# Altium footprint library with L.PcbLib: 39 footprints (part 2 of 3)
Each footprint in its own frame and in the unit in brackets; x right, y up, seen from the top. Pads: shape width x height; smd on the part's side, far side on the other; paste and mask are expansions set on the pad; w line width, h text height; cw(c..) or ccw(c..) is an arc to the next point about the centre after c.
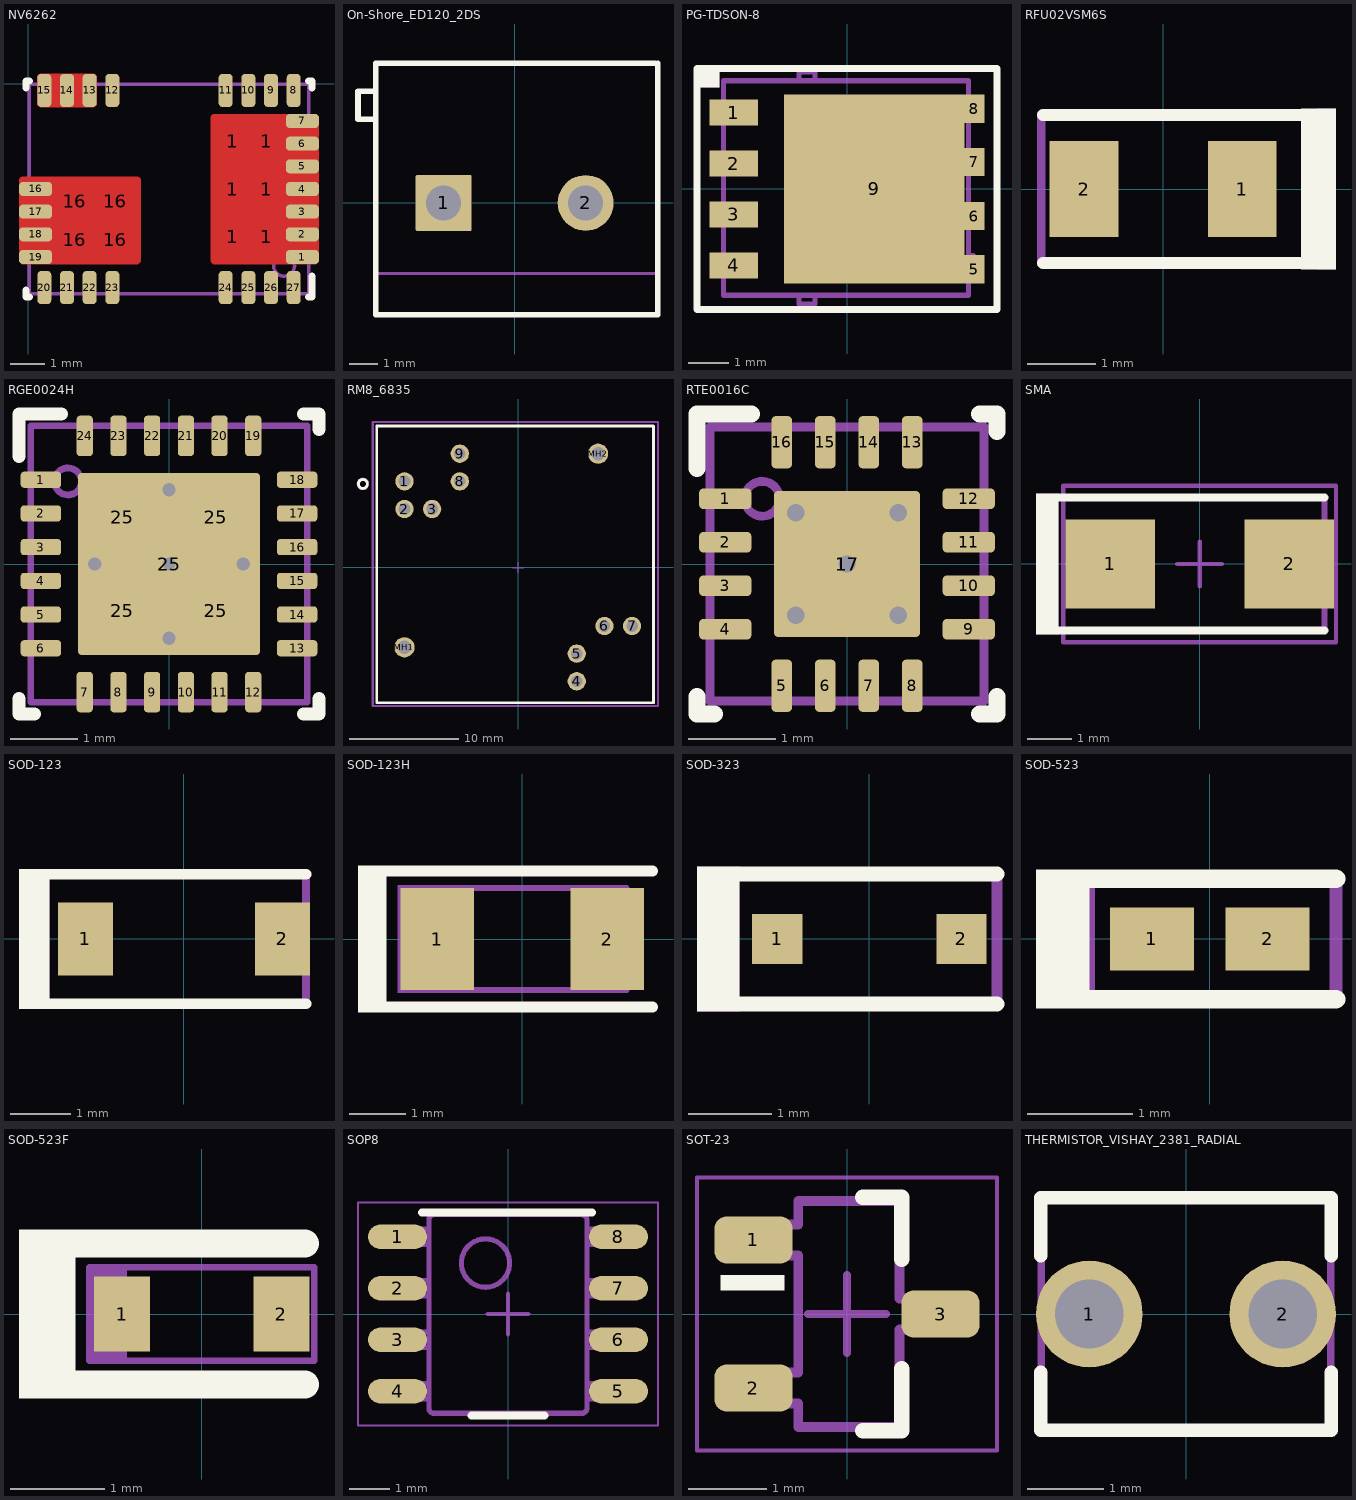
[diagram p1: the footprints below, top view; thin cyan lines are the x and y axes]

## NV6262 [mm]
pads (37):
  rrect50% 0.78x1.17 on Top Paste: 1(5.858,-4.384) 1(5.858,-3.014) 1(5.858,-1.644) 1(6.838,-4.384) 1(6.838,-3.014) 1(6.838,-1.644)
  rrect55% 0.95x0.4 smd paste-0.05 mask-0.05: 1(7.858,-4.964) 2(7.858,-4.314) 3(7.858,-3.664) 4(7.858,-3.014) 5(7.858,-2.364) 6(7.858,-1.714) 7(7.858,-1.064) 16(0.208,-3.014) 17(0.208,-3.664) 18(0.208,-4.314) 19(0.208,-4.964)
  rrect55% 0.4x0.95 smd paste-0.05 mask-0.05: 8(7.608,-0.189) 9(6.958,-0.189) 10(6.308,-0.189) 11(5.658,-0.189) 12(2.408,-0.189) 13(1.758,-0.189) 14(1.108,-0.189) 15(0.458,-0.189) 20(0.458,-5.839) 21(1.108,-5.839) 22(1.758,-5.839) 23(2.408,-5.839) 24(5.658,-5.839) 25(6.308,-5.839) 26(6.958,-5.839) 27(7.608,-5.839)
  rrect50% 0.96x0.9 on Top Paste: 16(1.333,-4.464) 16(1.333,-3.364) 16(2.493,-4.464) 16(2.493,-3.364)
Top Layer:
  region: 1.958,0.186 1.958,-0.564 1.958,-0.584 1.943,-0.621 1.915,-0.649 1.878,-0.664 1.858,-0.664 0.358,-0.664 0.339,-0.664 0.302,-0.649 0.274,-0.621 0.258,-0.584 0.258,-0.564 0.258,0.186 0.258,0.206 0.274,0.242 0.302,0.271 0.339,0.286 0.358,0.286 1.858,0.286 1.878,0.286 1.915,0.271 1.943,0.242 1.958,0.206
  region: 8.333,-0.964 8.333,-5.064 8.333,-5.084 8.318,-5.121 8.29,-5.149 8.253,-5.164 8.233,-5.164 5.323,-5.164 5.304,-5.164 5.267,-5.149 5.239,-5.121 5.223,-5.084 5.223,-5.064 5.223,-0.964 5.223,-0.944 5.239,-0.908 5.267,-0.879 5.304,-0.864 5.323,-0.864 8.233,-0.864 8.253,-0.864 8.29,-0.879 8.318,-0.908 8.333,-0.944
  region: 3.223,-2.764 3.223,-5.064 3.223,-5.084 3.208,-5.121 3.18,-5.149 3.143,-5.164 3.123,-5.164 -0.167,-5.164 -0.186,-5.164 -0.223,-5.149 -0.251,-5.121 -0.267,-5.084 -0.267,-5.064 -0.267,-2.764 -0.267,-2.744 -0.251,-2.708 -0.223,-2.679 -0.186,-2.664 -0.167,-2.664 3.123,-2.664 3.143,-2.664 3.18,-2.679 3.208,-2.708 3.223,-2.744
Top Overlay:
  lines w0.2: -0.067,-5.914 -0.067,-6.114 0.033,-6.114 ; -0.067,-0.114 -0.067,0.086 0.033,0.086 ; 8.033,-6.114 8.133,-6.114 8.133,-5.514 ; 8.033,0.086 8.133,0.086 8.133,-0.114
Top Paste:
  region: 1.759,-0.164 0.459,-0.164 0.459,-0.614 1.759,-0.614
Top Solder:
  region: 7.533,-4.814 7.233,-4.814 7.233,-5.114 7.533,-5.114
  region: 7.533,-4.164 7.233,-4.164 7.233,-4.464 7.533,-4.464
  region: 7.533,-3.514 7.233,-3.514 7.233,-3.814 7.533,-3.814
  region: 7.533,-2.864 7.233,-2.864 7.233,-3.164 7.533,-3.164
  region: 7.533,-2.214 7.233,-2.214 7.233,-2.514 7.533,-2.514
  region: 7.533,-1.564 7.233,-1.564 7.233,-1.864 7.533,-1.864
  region: 7.533,-0.914 7.233,-0.914 7.233,-1.214 7.533,-1.214
  region: 0.834,-4.164 0.534,-4.164 0.534,-4.464 0.834,-4.464
  region: 0.834,-4.814 0.534,-4.814 0.534,-5.114 0.834,-5.114
  region: 0.834,-3.514 0.534,-3.514 0.534,-3.814 0.834,-3.814
  region: 0.834,-2.864 0.534,-2.864 0.534,-3.164 0.834,-3.164
  region: 1.759,-0.164 0.459,-0.164 0.459,-0.614 1.759,-0.614
  region: 7.433,-0.964 7.433,-5.064 7.433,-5.074 7.426,-5.093 7.412,-5.107 7.393,-5.114 7.383,-5.114 5.323,-5.114 5.313,-5.114 5.295,-5.107 5.281,-5.093 5.273,-5.074 5.273,-5.064 5.273,-0.964 5.273,-0.954 5.281,-0.936 5.295,-0.922 5.313,-0.914 5.323,-0.914 7.383,-0.914 7.393,-0.914 7.412,-0.922 7.426,-0.936 7.433,-0.954
  region: 3.173,-2.764 3.173,-5.064 3.173,-5.074 3.166,-5.093 3.152,-5.107 3.133,-5.114 3.123,-5.114 0.683,-5.114 0.673,-5.114 0.655,-5.107 0.641,-5.093 0.633,-5.074 0.633,-5.064 0.633,-2.764 0.633,-2.754 0.641,-2.736 0.655,-2.722 0.673,-2.714 0.683,-2.714 3.123,-2.714 3.133,-2.714 3.152,-2.722 3.166,-2.736 3.173,-2.754
Mechanical 6:
  circle w0.1: c7.333,-5.214 r0.3
  lines w0.1: 0.033,-6.014 8.033,-6.014 8.033,-0.014 0.033,-0.014 0.033,-6.014
  text ".Designator" at 9.29,-2.159 h1.02
3D body: height 0.9, standoff 0, extent 0.033,-6.014 8.033,-0.014
3D body: height 0.91, standoff 0.9, extent 7.034,-5.514 7.633,-4.915

## On-Shore_ED120_2DS [mm] "ONSHORE"
height 13
pads (2):
  rrect5% 2x2 hole 1.25: 1(-2.54,0)
  round 2 hole 1.25: 2(2.54,0)
Top Overlay:
  lines w0.2: -4.96,-4 -4.96,5 5.015,5 ; -4.96,3 -5.6,3 -5.6,4 -4.96,4 ; -4.885,-4 5.115,-4 5.115,5
Mechanical 5:
  lines w0.1: -4.96,-4 -4.96,5 5.115,5 5.115,-4 -4.885,-4 ; -4.96,3 -5.6,3 -5.6,4 -4.96,4 ; -4.875,-2.525 5.125,-2.525
3D body "ED1202DS.stp": height 13, standoff -4, extent -5.78,-4 5.08,5

## PG-TDSON-8 [mm] "Infineon recommended land pattern"
height 1.1
pads (9):
  rect 1.2x0.65 smd: 1(-2.825,1.905) 2(-2.825,0.635) 3(-2.825,-0.635) 4(-2.825,-1.905)
  rect 0.5x0.7 smd: 5(3.175,-2) 6(3.175,-0.675) 7(3.175,0.675) 8(3.175,2)
  rect 4.5x4.7 smd paste-2.25: 9(0.675,0)
Top Overlay:
  rectangle: -3.74,2.527 -3.175,2.975
  lines w0.178: -3.74,-3 -0.105,-3 3.74,-3 3.74,0 3.74,3 0.105,3 -3.74,3 -3.74,0 -3.74,-3
Top Paste:
  rectangle: -1.475,-2.25 -0.242,-0.95
  rectangle: 0.058,-2.25 1.291,-0.95
  rectangle: 1.591,-2.25 2.824,-0.95
  rectangle: 1.591,-0.65 2.824,0.65
  rectangle: 0.058,-0.65 1.291,0.65
  rectangle: -1.475,-0.65 -0.242,0.65
  rectangle: 1.591,0.95 2.824,2.25
  rectangle: 0.058,0.95 1.291,2.25
  rectangle: -1.475,0.95 -0.242,2.25
Mechanical 5:
  rectangle: -3.74,2.527 -3.175,2.975
  lines w0.127: -3.075,-2.1 -3.2,-2.1 -3.2,-1.66 -3.075,-1.66 ; -3.075,-0.83 -3.2,-0.83 -3.2,-0.39 -3.075,-0.39 ; -3.075,0.44 -3.2,0.44 -3.2,0.88 -3.075,0.88 ; -3.075,1.71 -3.2,1.71 -3.2,2.15 -3.075,2.15 ; -1.2,-2.65 -1.2,-2.87 -0.8,-2.87 -0.8,-2.65 ; -1.2,2.7 -1.2,2.92 -0.8,2.92 -0.8,2.7 ; 3.025,-2.1 3.15,-2.1 3.15,-1.66 3.025,-1.66 ; 3.025,-0.83 3.15,-0.83 3.15,-0.39 3.025,-0.39 ; 3.025,0.44 3.15,0.44 3.15,0.88 3.025,0.88 ; 3.025,1.71 3.15,1.71 3.15,2.15 3.025,2.15 ; -3.075,-2.65 -3.075,2.7 3.025,2.7 3.025,-2.65 -3.075,-2.65
3D body "PG-TDSON-8.stp": height 1.1, standoff 0, extent -3.175,-2.895 3.175,2.895

## RFU02VSM6S [mm] "On Semi recommended land pattern"
height 1.35
pads (2):
  rect 1x1.4 smd: 1(1.15,0) 2(-1.15,0)
Top Overlay:
  region: 2.515,1.168 2.007,1.168 2.007,-1.168 2.515,-1.168
  lines w0.178: -1.75,-1.075 2.4,-1.075 ; -1.75,1.075 2.425,1.075
Mechanical 6:
  region: 2.489,1.169 2.235,1.169 2.235,-1.168 2.489,-1.168
  lines w0.127: -1.775,1.075 2.45,1.075 ; -1.775,1.084 -1.775,-1.075 2.413,-1.079
  text ".Designator" at 1.956,0.33 h0.76
3D body "SOD-123.stp": height 1.35, standoff 0, extent -1.932,-0.9 1.932,0.9

## RGE0024H [mm] "QFN, 24-Leads, Body 4x4mm, Pitch 0.5mm, Thermal Pad 2.7x2.7mm, TI Recommended"
height 1
pads (29):
  rrect42% 0.6x0.24 smd: 1(-1.9,1.25) 2(-1.9,0.75) 3(-1.9,0.25) 4(-1.9,-0.25) 5(-1.9,-0.75) 6(-1.9,-1.25) 13(1.9,-1.25) 14(1.9,-0.75) 15(1.9,-0.25) 16(1.9,0.25) 17(1.9,0.75) 18(1.9,1.25)
  rrect42% 0.24x0.6 smd: 7(-1.25,-1.9) 8(-0.75,-1.9) 9(-0.25,-1.9) 10(0.25,-1.9) 11(0.75,-1.9) 12(1.25,-1.9) 19(1.25,1.9) 20(0.75,1.9) 21(0.25,1.9) 22(-0.25,1.9) 23(-0.75,1.9) 24(-1.25,1.9)
  rrect50% 1.19x1.19 on Top Paste: 25(-0.695,-0.695) 25(-0.695,0.695) 25(0.695,-0.695) 25(0.695,0.695)
  rrect4% 2.7x2.7 smd paste-1.35: 25(0,0)
via 0,-1.1 diameter 0.5 hole 0.2
via 0,1.1 diameter 0.5 hole 0.2
via -1.1,0 diameter 0.5 hole 0.2
via 0,0 diameter 0.5 hole 0.2
via 1.1,0 diameter 0.5 hole 0.2
Top Overlay:
  lines w0.2: -2.225,-2 -2.225,-2.225 -2,-2.225 ; -2.225,1.6 -2.225,2.225 -1.6,2.225 ; 2,-2.225 2.225,-2.225 2.225,-2 ; 2,2.225 2.225,2.225 2.225,2
Mechanical 5:
  circle w0.1: c-1.5,1.225 r0.2
  lines w0.1: -2.05,-2.05 2.05,-2.05 2.05,2.05 -2.05,2.05 -2.05,-2.05
3D body: height 1, standoff 0, extent -2.075,-2.075 2.075,2.075
3D body: height 1.01, standoff 0.5, extent -1.699,1.026 -1.301,1.424

## RM8_6835 [mm] "THT, Body 24.64X24.64mm, 10Pin, Pitch 2.54mm"
height 17.32
pads (12):
  round 1.68 hole 1.07: 1(-10.45,7.91) 2(-10.45,5.37) 3(-7.91,5.37) 4(5.37,-10.45) 5(5.37,-7.91) 6(7.91,-5.37) 7(10.45,-5.37) 8(-5.37,7.91) 9(-5.37,10.45)
  round 0 all layers, no hole: 10(-7.91,10.45)
  round 1.86 hole 1.25: MH1(-10.45,-7.33) MH2(7.33,10.45)
Top Overlay:
  circle w0.254: c-14.27,7.67 r0.412
  lines w0.254: -12.99,-12.41 12.41,-12.41 12.41,12.99 -12.99,12.99 -12.99,-12.41
Mechanical 13:
  circle w0.254: c-14.27,7.67 r0.447
Mechanical 15:
  lines w0.1: -0.495,-0.005 0.505,-0.005 ; 0.005,-0.505 0.005,0.495
  lines w0.2: -13.37,-12.73 12.83,-12.73 12.83,13.37 -13.37,13.37 -13.37,-12.73
3D body "RM8_6835.STEP": height 16.79, standoff -3.46, extent -12.35,-12.148 12.197,12.398

## RTE0016C [mm] "Texas Insturments"
height 0.8
pads (18):
  rrect42% 0.6x0.24 smd: 1(-1.4,0.75) 2(-1.4,0.25) 3(-1.4,-0.25) 4(-1.4,-0.75) 9(1.4,-0.75) 10(1.4,-0.25) 11(1.4,0.25) 12(1.4,0.75)
  rrect42% 0.24x0.6 smd: 5(-0.75,-1.4) 6(-0.25,-1.4) 7(0.25,-1.4) 8(0.75,-1.4) 13(0.75,1.4) 14(0.25,1.4) 15(-0.25,1.4) 16(-0.75,1.4)
  rrect50% 1.55x1.55 on Top Paste: 17(0,0)
  rrect6% 1.68x1.68 smd paste-0.85: 17(0,0)
via 0,0 diameter 0.5 hole 0.2
via -0.59,0.59 diameter 0.5 hole 0.2
via -0.59,-0.59 diameter 0.5 hole 0.2
via 0.59,-0.59 diameter 0.5 hole 0.2
via 0.59,0.59 diameter 0.5 hole 0.2
Top Overlay:
  lines w0.2: -1.725,-1.525 -1.725,-1.725 -1.525,-1.725 ; -1.725,1.1 -1.725,1.725 -1.1,1.725 ; 1.525,-1.725 1.725,-1.725 1.725,-1.525 ; 1.525,1.725 1.725,1.725 1.725,1.525
Mechanical 5:
  circle w0.1: c-0.975,0.75 r0.2
  lines w0.1: -1.575,-1.575 -1.575,1.575 1.575,1.575 1.575,-1.575 -1.575,-1.575
3D body: height 0.8, standoff 0, extent -1.575,-1.575 1.575,1.575
3D body: height 0.81, standoff 0.5, extent -1.174,0.551 -0.776,0.949

## SMA [mm] "Molded Diode, 2-Leads, Body 4.3x2.6mm, IPC Medium Density, based on OnSemi component dimensions and land pattern"
height 2.27
pads (2):
  rect 2x2 smd: 1(-2,0) 2(2,0)
Top Overlay:
  rectangle: -3.658,-1.575 -3.15,1.575
  lines w0.178: -3.327,-1.486 2.794,-1.486 ; -3.327,1.486 2.794,1.486
Mechanical 5:
  rectangle: -3.658,-1.575 -3.15,1.575
  lines w0.127: -3.327,-1.486 2.794,-1.486 2.794,1.486 -3.327,1.486
Mechanical 15:
  lines w0.1: -0.5,0 0.5,0 ; 0,-0.5 0,0.5 ; -3.05,-1.75 -3.05,1.75 3.05,1.75 3.05,-1.75 -3.05,-1.75
3D body "SMA_nominal.stp": height 2.42, standoff 0.02, extent -2.6,-1.3 2.6,1.3

## SOD-123 [mm] "On Semi recommended land pattern"
height 1.35
pads (2):
  rect 0.915x1.22 smd: 1(-1.637,0) 2(1.637,0)
Top Overlay:
  rectangle: -2.743,-1.169 -2.235,1.168
  lines w0.178: -2.413,-1.079 2.032,-1.079 ; -2.413,1.079 2.032,1.079
Mechanical 5:
  rectangle: -2.743,-1.169 -2.235,1.168
  lines w0.127: -2.413,-1.079 2.032,-1.079 2.032,1.079 -2.413,1.079
3D body "SOD-123.stp": height 1.35, standoff 0, extent -1.932,-0.9 1.932,0.9

## SOD-123H [mm] "SMT, 2-Leads, Body 3.5x1.6mm"
height 1
pads (2):
  rect 1.3x1.8 smd: 1(-1.5,0) 2(1.5,0)
Top Overlay:
  rectangle: -2.9,-1.3 -2.4,1.3
  lines w0.2: -2.5,-1.2 2.3,-1.2 ; -2.5,1.2 2.3,1.2
Mechanical 5:
  rectangle: -2.2,-0.95 -1.8,0.95
  lines w0.1: -1.85,-0.9 -1.85,0.9 1.85,0.9 1.85,-0.9 -1.85,-0.9
3D body "SOD-123FL.stp": height 1, standoff 0, extent -1.9,-0.9 1.9,0.9

## SOD-323 [mm] "NXP recommended land pattern"
height 1.15
pads (2):
  rect 0.6x0.6 smd paste-0.05: 1(-1.1,0) 2(1.1,0)
Top Overlay:
  rectangle: -2.057,-0.864 -1.549,0.863
  lines w0.178: -1.803,-0.775 0.1,-0.775 1.525,-0.775 ; -1.803,0.775 0.1,0.775 1.525,0.775
Mechanical 5:
  rectangle: -2.057,-0.864 -1.549,0.863
  lines w0.127: -1.803,-0.775 0.1,-0.775 1.525,-0.775 1.525,0.775 0.1,0.775 -1.803,0.775
3D body "SOD-323.stp": height 1.1, standoff 0, extent -1.3,-0.675 1.3,0.675

## SOD-523 [mm] "NXP Semiconductor recommended land pattern, nominal STEP model"
height 0.7
pads (2):
  rect 0.8x0.6 smd paste-0.05: 1(-0.55,0) 2(0.55,0)
Top Overlay:
  rectangle: -1.651,-0.661 -1.143,0.66
  lines w0.178: -1.475,-0.572 0,-0.572 1.2,-0.572 ; -1.475,0.572 0,0.572 1.2,0.572
Mechanical 5:
  rectangle: -1.6,-0.635 -1.092,0.635
  lines w0.127: -1.475,-0.546 0,-0.546 1.2,-0.546 1.2,0.546 0,0.559 -1.475,0.559
3D body "SOD-523F.stp": height 0.72, standoff 0.02, extent -0.8,-0.399 0.8,0.399

## SOD-523F [mm] "COMCHIP"
height 0.85
pads (2):
  rect 0.6x0.8 smd paste-0.05: 1(-0.85,0) 2(0.85,0)
Top Overlay:
  rectangle: -1.949,-0.9 -1.349,0.9
  lines w0.3: -1.5,-0.75 1.1,-0.75 ; -1.5,0.75 1.1,0.75
Mechanical 5:
  rectangle: -1.2,-0.5 -0.8,0.5
  lines w0.07: -1.2,-0.5 -1.2,0.5 1.2,0.5 1.2,-0.5 -1.2,-0.5
3D body: height 0.85, standoff 0.84, extent -0.899,-0.499 -0.401,0.499
3D body: height 0.85, standoff 0, extent -0.899,-0.499 0.899,0.499

## SOP8 [mm] "SOIC, 8-Leads, Body 4.9x3.9mm, Pitch 1.27mm, IPC Medium Density"
height 1.75
pads (8):
  oval 1.45x0.6 smd: 1(-2.725,1.905) 2(-2.725,0.635) 3(-2.725,-0.635) 4(-2.725,-1.905) 5(2.725,-1.905) 6(2.725,-0.635) 7(2.725,0.635) 8(2.725,1.905)
Top Overlay:
  lines w0.2: -2.125,2.5 2.075,2.5 ; -0.9,-2.5 0.9,-2.5
Mechanical 5:
  lines w0.127: -2.375,-2.095 -2.375,-1.715 ; -2.375,-2.095 -2.589,-2.095 -3.002,-2.095 -3.002,-1.715 -2.589,-1.715 -2.375,-1.715 ; -2.375,-2.095 -1.995,-2.095 -1.952,-2.095 -1.952,-1.715 -1.995,-1.715 -2.375,-1.715 ; -2.375,-0.825 -2.375,-0.445 ; -2.375,-0.825 -2.589,-0.825 -3.002,-0.825 -3.002,-0.445 -2.589,-0.445 -2.375,-0.445 ; -2.375,-0.825 -1.995,-0.825 -1.952,-0.825 -1.952,-0.445 -1.995,-0.445 -2.375,-0.445 ; -2.375,0.445 -2.375,0.825 ; -2.375,0.445 -2.589,0.445 -3.002,0.445 -3.002,0.825 -2.589,0.825 -2.375,0.825 ; -2.375,0.445 -1.995,0.445 -1.952,0.445 -1.952,0.825 -1.995,0.825 -2.375,0.825 ; -2.375,1.715 -2.375,2.095 ; -2.375,1.715 -2.589,1.715 -3.002,1.715 -3.002,2.095 -2.589,2.095 -2.375,2.095 ; -2.375,1.715 -1.995,1.715 -1.952,1.715 -1.952,2.095 -1.995,2.095 -2.375,2.095 ; -0.332,-2.45 -0.182,-2.45 ; -0.332,-2.45 -0.182,-2.45 ; -0.332,-2.45 -1.825,-2.45 -1.826,-2.45 cw(c-1.825,-2.323) -1.952,-2.324 -1.952,-2.323 -1.952,2.323 -1.952,2.324 cw(c-1.825,2.323) -1.826,2.45 -1.825,2.45 -0.332,2.45 ; -0.332,2.45 -0.182,2.45 ; -0.332,2.45 -0.182,2.45 ; -0.182,-2.45 0.178,-2.45 ; -0.182,2.45 0.178,2.45 ; 0.178,-2.45 0.328,-2.45 ; 0.178,-2.45 0.328,-2.45 ; 0.178,2.45 0.328,2.45 ; 0.178,2.45 0.328,2.45 ; 0.328,-2.45 1.821,-2.45 1.822,-2.45 ccw(c1.821,-2.323) 1.948,-2.324 1.948,-2.323 1.948,2.323 1.948,2.324 ccw(c1.821,2.323) 1.822,2.45 1.821,2.45 0.328,2.45 ; 2.371,-2.095 2.371,-1.715 ; 2.371,-2.095 1.991,-2.095 1.948,-2.095 1.948,-1.715 1.991,-1.715 2.371,-1.715 ; 2.371,-2.095 2.585,-2.095 2.998,-2.095 2.998,-1.715 2.585,-1.715 2.371,-1.715 ; 2.371,-0.825 2.371,-0.445 ; 2.371,-0.825 1.991,-0.825 1.948,-0.825 1.948,-0.445 1.991,-0.445 2.371,-0.445 ; 2.371,-0.825 2.585,-0.825 2.998,-0.825 2.998,-0.445 2.585,-0.445 2.371,-0.445 ; 2.371,0.445 2.371,0.825 ; 2.371,0.445 1.991,0.445 1.948,0.445 1.948,0.825 1.991,0.825 2.371,0.825 ; 2.371,0.445 2.585,0.445 2.998,0.445 2.998,0.825 2.585,0.825 2.371,0.825 ; 2.371,1.715 2.371,2.095 ; 2.371,1.715 1.991,1.715 1.948,1.715 1.948,2.095 1.991,2.095 2.371,2.095 ; 2.371,1.715 2.585,1.715 2.998,1.715 2.998,2.095 2.585,2.095 2.371,2.095 ; -0.555,0.659 ccw(c-0.555,1.256) -0.555,1.853 ccw(c-0.555,1.256) -0.555,0.659
  text ".Designator" at -1.625,-0.625 h0.89
Mechanical 15:
  lines w0.05: -3.7,-2.75 -3.7,2.75 3.7,2.75 3.7,-2.75 -3.7,-2.75
  lines w0.1: -0.5,0 0.5,0 ; 0,-0.5 0,0.5
3D body "D0008A.stp": height 1.63, standoff 0, extent -3,-2.45 3,2.45

## SOT-23 [mm] "SOT23, 3-Leads, Body 2.9x1.3mm, Pitch 0.95mm, Lead Span 2.5mm, IPC Medium Density"
height 1.1
pads (3):
  rrect50% 1x0.6 smd: 1(-1.2,0.95) 2(-1.2,-0.95) 3(1.2,0)
Top Overlay:
  rectangle: -1.625,0.3 -0.8,0.5
  lines w0.2: 0.2,-1.5 0.7,-1.5 0.7,-0.7 ; 0.2,1.5 0.7,1.5 0.7,0.7
Mechanical 5:
  lines w0.127: -1.16,-1.15 -1.16,-0.75 -0.625,-0.75 -0.625,0.75 -1.16,0.75 -1.16,1.15 -0.625,1.15 -0.625,1.45 0.675,1.45 0.675,0.2 1.21,0.2 1.21,-0.2 0.675,-0.2 0.675,-1.45 -0.625,-1.45 -0.625,-1.15 -1.16,-1.15
  text ".Designator" at -0.175,1.225 h0.64
Mechanical 15:
  lines w0.05: -1.925,-1.75 1.925,-1.75 1.925,1.75 -1.925,1.75 -1.925,-1.75
  lines w0.1: -0.5,0 0.5,0 ; 0,-0.5 0,0.5
3D body "SW3dPS-sot-3p290x130ll237h100.STEP": height 1, standoff 0, extent -1.16,-1.45 1.21,1.45

## THERMISTOR_VISHAY_2381_RADIAL [mm] "Vishay 2381 series thermistors"
height 9
pads (2):
  round 1.4 hole 0.9: 1(-1.27,0) 2(1.27,0)
Top Overlay:
  lines w0.178: -1.905,-0.762 -1.905,-1.524 1.905,-1.524 1.905,-0.762 ; -1.905,0.762 -1.905,1.524 1.905,1.524 1.905,0.762
Mechanical 5:
  lines w0.102: -1.9,-1.5 0,-1.5 1.9,-1.5 1.9,0 1.9,1.5 0,1.5 -1.9,1.5 -1.9,0 -1.9,-1.5
3D body: height 9, standoff 0, extent -1.899,-1.499 1.899,1.499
